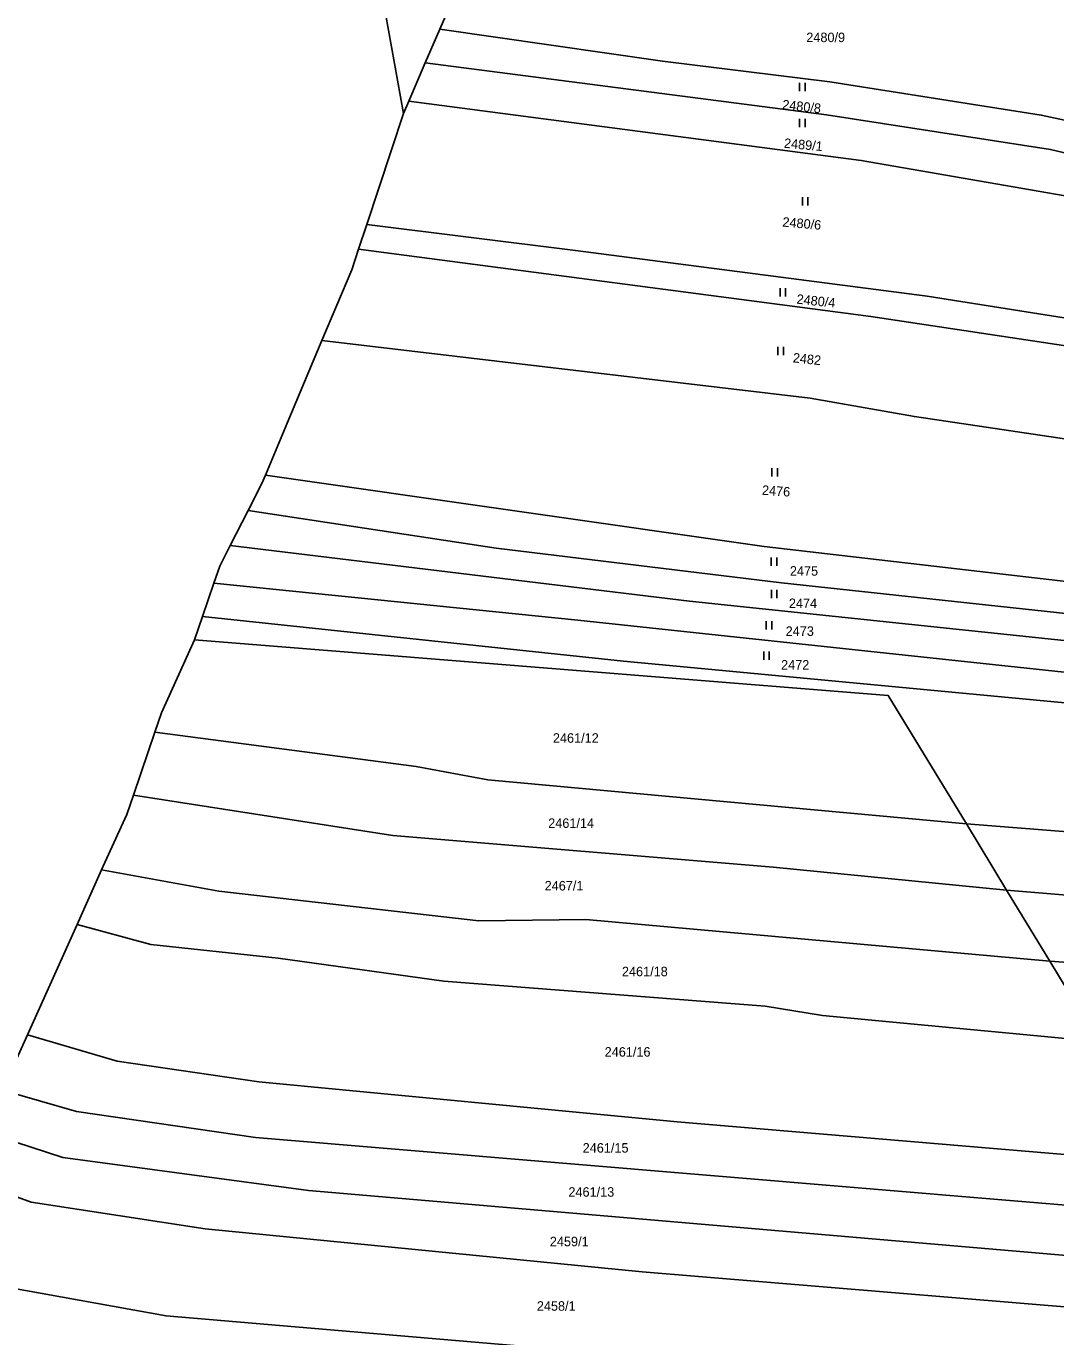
# Model space of a CAD drawing. Extents: x -755528 to -748832, y -1118122 to -1111095.
# Drawn here: x -754328.8 to -754144.3, y -1115420.3 to -1115185.5 of the extents above; entities that cross this region are included whole.
import ezdxf

# ---------------------------------------------------------------- set-up
doc = ezdxf.new("R2010")
doc.units = 0
for name, color, linetype in [('DZ_DO_PUPFL', 7, 'Continuous'), ('DZ_NAD_PUPFL', 7, 'Continuous'), ('DZ_NAD_ZPF', 7, 'Continuous'), ('TZ_UMVŽST', 7, 'Continuous')]:
    doc.layers.add(name, color=color, linetype=linetype)

msp = doc.modelspace()

# ---------------------------------------------------------------- linework, layer by layer
at = {"layer": 'DZ_NAD_PUPFL'}
for p, q in [((-754261.23, -1115201.12), (-754273.06, -1115135.48)), ((-754267.8, -1115221), (-754261.23, -1115201.12)), ((-754269.26, -1115225.42), (-754267.8, -1115221)), ((-754292.27, -1115278.55), (-754289.06, -1115272.27)), ((-754297.26, -1115291.28), (-754295.19, -1115285.27)), ((-754298.69, -1115295.44), (-754297.26, -1115291.28)), ((-754304.57, -1115308.51), (-754298.69, -1115295.44)), ((-754305.77, -1115312), (-754304.57, -1115308.51)), ((-754306.96, -1115315.52), (-754305.77, -1115312)), ((-754309.62, -1115323.31), (-754306.96, -1115315.52)), ((-754319.7, -1115346.45), (-754315.31, -1115336.68)), ((-754328.62, -1115366.25), (-754319.7, -1115346.45)), ((-754333.08, -1115376.16), (-754328.62, -1115366.25))]:
    msp.add_line(p, q, dxfattribs=at)
for points in [[(-754275.83, -1115241.84), (-754270.49, -1115229.15), (-754269.26, -1115225.42)], [(-754285.97, -1115265.95), (-754282.05, -1115256.61), (-754275.83, -1115241.84)], [(-754289.06, -1115272.27), (-754286.59, -1115267.42), (-754285.97, -1115265.95)], [(-754295.19, -1115285.27), (-754294.15, -1115282.24), (-754292.27, -1115278.55)], [(-754315.31, -1115336.68), (-754313.77, -1115333.26), (-754310.79, -1115326.75), (-754309.62, -1115323.31)]]:
    msp.add_lwpolyline(points, dxfattribs=at)
at = {"layer": 'DZ_NAD_ZPF'}
for p, q in [((-754254.67, -1115186), (-754257.31, -1115192.08)), ((-754257.31, -1115192.08), (-754260.27, -1115198.91)), ((-754260.27, -1115198.91), (-754261.23, -1115201.12)), ((-754153.1, -1115340.3), (-754160.31, -1115328.45)), ((-754145.36, -1115353.03), (-754153.1, -1115340.3))]:
    msp.add_line(p, q, dxfattribs=at)
for points in [[(-754239.5, -1115144.23), (-754239.69, -1115148.14), (-754241.55, -1115155.78), (-754254.67, -1115186)], [(-754130.19, -1115205.02), (-754146.91, -1115201.42), (-754184.82, -1115195.45), (-754214.8, -1115191.74), (-754254.67, -1115186)], [(-754257.31, -1115192.08), (-754185.38, -1115201.37), (-754145.22, -1115207.61), (-754130.35, -1115211.11)], [(-754126.07, -1115218.74), (-754179.17, -1115209.53), (-754260.27, -1115198.91)], [(-754108.38, -1115244.07), (-754127.34, -1115240.21), (-754167.34, -1115233.89), (-754230.39, -1115225.67), (-754267.8, -1115221)], [(-754269.26, -1115225.42), (-754177.42, -1115237.52), (-754123.1, -1115245.7), (-754104.84, -1115247.96)], [(-754084.81, -1115266.24), (-754122.67, -1115262.43), (-754169.64, -1115255.43), (-754188.29, -1115252.17), (-754275.83, -1115241.84)], [(-754048.51, -1115293.96), (-754095.53, -1115290.42), (-754196.54, -1115278.7), (-754285.97, -1115265.95)], [(-754038.27, -1115298.64), (-754081.34, -1115296.95), (-754133.64, -1115291.7), (-754193.47, -1115285.24), (-754244.62, -1115279.05), (-754289.06, -1115272.27)], [(-754027.71, -1115304.46), (-754105.26, -1115299.53), (-754209.94, -1115288.54), (-754292.27, -1115278.55)], [(-754017.52, -1115310.43), (-754031.7, -1115310.11), (-754128.79, -1115302.73), (-754229.97, -1115291.92), (-754295.19, -1115285.27)], [(-754005.81, -1115318.43), (-754098.4, -1115309.64), (-754137.62, -1115307.23), (-754221.78, -1115299.27), (-754297.26, -1115291.28)], [(-754298.69, -1115295.44), (-754174.31, -1115305.44), (-754160.31, -1115328.45)], [(-754305.77, -1115312), (-754258.91, -1115318.16), (-754246.09, -1115320.56), (-754160.31, -1115328.45)], [(-754309.62, -1115323.31), (-754263.09, -1115330.49), (-754194.97, -1115336.17), (-754153.1, -1115340.3)], [(-754160.31, -1115328.45), (-754098.39, -1115333.3), (-754057.22, -1115336.3), (-754011.58, -1115342.12), (-753971.2, -1115345.33)], [(-754145.36, -1115353.03), (-754228.54, -1115345.58), (-754247.68, -1115345.8), (-754294.32, -1115340.48), (-754315.31, -1115336.68)], [(-753951.24, -1115358.93), (-753994.61, -1115354.32), (-754031.9, -1115351.27), (-754069.5, -1115347.43), (-754098.22, -1115344.83), (-754153.1, -1115340.3)], [(-754138.12, -1115367.33), (-754186.12, -1115362.74), (-754196.4, -1115361.1), (-754253.97, -1115356.6), (-754283.66, -1115352.47), (-754306.51, -1115350.07), (-754319.7, -1115346.45)], [(-754145.36, -1115353.03), (-754141.22, -1115359.83), (-754138.12, -1115367.33)], [(-753917.05, -1115375.84), (-753986.98, -1115365.95), (-754004.12, -1115364.66), (-754033.48, -1115361.27), (-754145.36, -1115353.03)], [(-754129.23, -1115388.82), (-754212.17, -1115381.81), (-754287.12, -1115374.67), (-754312.52, -1115370.96), (-754328.62, -1115366.25)], [(-754125.36, -1115398.17), (-754287.76, -1115384.65), (-754319.79, -1115379.99), (-754333.08, -1115376.16)], [(-754121.47, -1115407.57), (-754278.26, -1115394.12), (-754322.24, -1115388.2), (-754336.43, -1115383.6)], [(-754117.54, -1115417.07), (-754218.4, -1115408.7), (-754296.77, -1115400.97), (-754327.92, -1115396.21), (-754340.13, -1115391.82)], [(-754111.28, -1115432.2), (-754141.01, -1115430.44), (-754199.34, -1115425.46), (-754303.76, -1115416.6), (-754331.96, -1115411.53), (-754346.68, -1115406.37)]]:
    msp.add_lwpolyline(points, dxfattribs=at)
at = {"layer": 'TZ_UMVŽST'}
for p, q in [((-754190.221, -1115197.11), (-754190.221, -1115195.61)), ((-754189.22, -1115197.11), (-754189.22, -1115195.61)), ((-754190.201, -1115203.6), (-754190.201, -1115202.1)), ((-754189.2, -1115203.6), (-754189.2, -1115202.1)), ((-754189.711, -1115217.63), (-754189.711, -1115216.13)), ((-754188.71, -1115217.63), (-754188.71, -1115216.13)), ((-754193.721, -1115233.93), (-754193.721, -1115232.43)), ((-754192.72, -1115233.93), (-754192.72, -1115232.43)), ((-754194.101, -1115244.45), (-754194.101, -1115242.95)), ((-754193.1, -1115244.45), (-754193.1, -1115242.95)), ((-754195.201, -1115266.21), (-754195.201, -1115264.71)), ((-754194.2, -1115266.21), (-754194.2, -1115264.71)), ((-754195.311, -1115282.18), (-754195.311, -1115280.68)), ((-754194.31, -1115282.18), (-754194.31, -1115280.68)), ((-754195.271, -1115287.98), (-754195.271, -1115286.48)), ((-754194.27, -1115287.98), (-754194.27, -1115286.48)), ((-754196.191, -1115293.58), (-754196.191, -1115292.08)), ((-754195.19, -1115293.58), (-754195.19, -1115292.08)), ((-754196.641, -1115299.05), (-754196.641, -1115297.55)), ((-754195.64, -1115299.05), (-754195.64, -1115297.55))]:
    msp.add_line(p, q, dxfattribs=at)

# ---------------------------------------------------------------- texts
at = {"layer": 'DZ_DO_PUPFL'}
for s, p in [('2480/9', (-754189.01, -1115188.34)), ('2475', (-754191.95, -1115283.95)), ('2474', (-754192.13, -1115289.75)), ('2473', (-754192.71, -1115294.74)), ('2472', (-754193.53, -1115300.78)), ('2461/12', (-754234.43, -1115313.89)), ('2461/14', (-754235.27, -1115329.15)), ('2467/1', (-754235.91, -1115340.36)), ('2461/18', (-754222.06, -1115355.73)), ('2461/16', (-754225.15, -1115370.14)), ('2461/15', (-754229.09, -1115387.34)), ('2461/13', (-754231.65, -1115395.24)), ('2459/1', (-754234.98, -1115404.12)), ('2458/1', (-754237.31, -1115415.67))]:
    msp.add_text(s, height=1.7, dxfattribs=at).set_placement(p)
for s, rotation, p in [('2480/8', 354, (-754193.388, -1115200.355)), ('2489/1', 355, (-754193.064, -1115207.266)), ('2480/6', 355, (-754193.344, -1115221.386)), ('2480/4', 354, (-754190.818, -1115235.195)), ('2482', 354, (-754191.488, -1115245.715)), ('2476', 356, (-754196.999, -1115269.447))]:
    msp.add_text(s, height=1.7, rotation=rotation, dxfattribs=at).set_placement(p)

doc.saveas('drawing.dxf')
